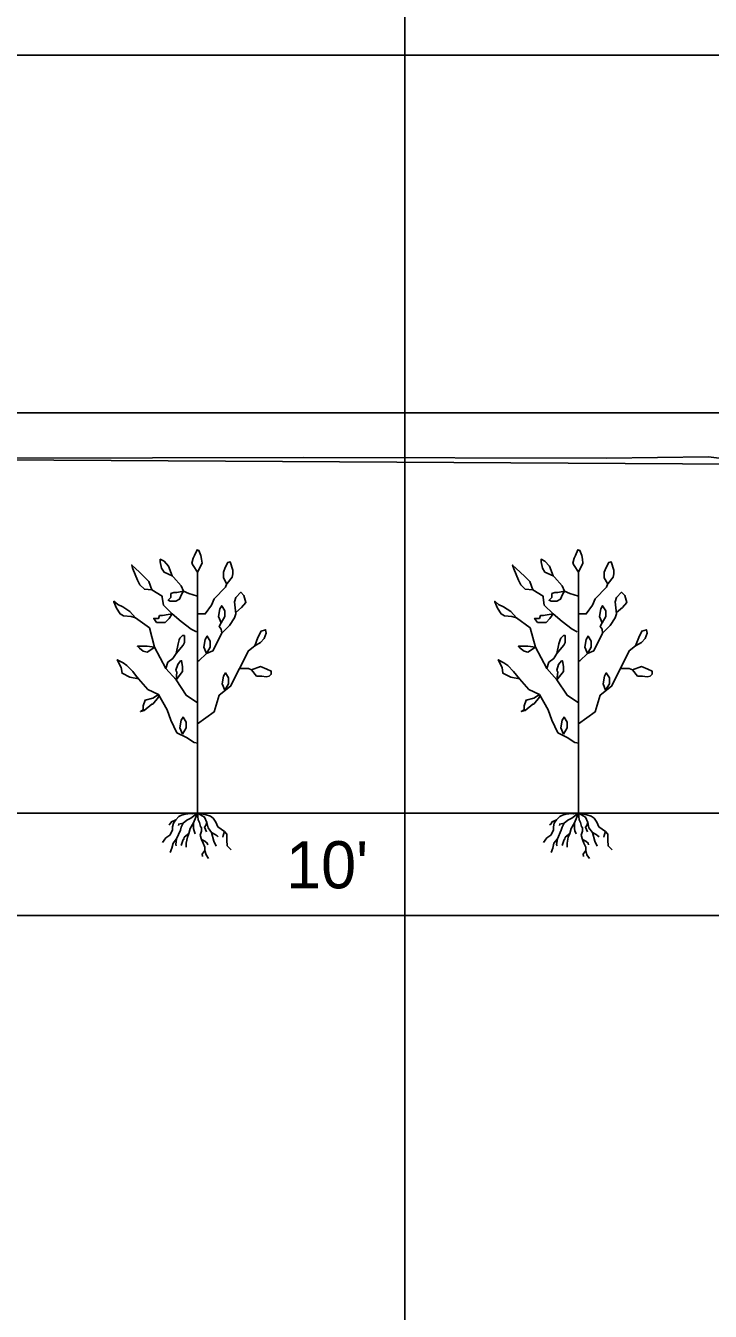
# Model space of a CAD drawing. Extents: x 1578769 to 1579225, y 724002 to 724828.
# Drawn here: x 1578852.46 to 1578859.27, y 724448.54 to 724461.32 of the extents above; entities that cross this region are included whole.
import ezdxf

# ---------------------------------------------------------------- set-up
doc = ezdxf.new("R2010")
doc.units = 0
for name, color, linetype in [('1', 7, 'Continuous'), ('Default', 7, 'Continuous'), ('Old_Level_41', 7, 'Continuous'), ('R_Exist Surface', 7, 'Continuous'), ('R_Fin Surface', 7, 'Continuous')]:
    doc.layers.add(name, color=color, linetype=linetype)

msp = doc.modelspace()

# ---------------------------------------------------------------- linework, layer by layer
at = {"layer": '1'}
for p, q in [((1578851.701, 724461.031), (1578861.706, 724461.031)), ((1578854.17, 724453.49), (1578854.17, 724455.89)), ((1578857.96, 724453.49), (1578857.96, 724455.89)), ((1578854.175, 724453.485), (1578854.177, 724453.489)), ((1578857.965, 724453.485), (1578857.966, 724453.489))]:
    msp.add_line(p, q, dxfattribs=at)
for points in [[(1578854.17, 724455.89), (1578854.126, 724455.953), (1578854.113, 724455.978), (1578854.126, 724456.029), (1578854.139, 724456.054), (1578854.164, 724456.111), (1578854.183, 724456.104), (1578854.202, 724456.054), (1578854.208, 724456.016), (1578854.214, 724455.978)], [(1578857.96, 724455.89), (1578857.916, 724455.953), (1578857.903, 724455.978), (1578857.916, 724456.029), (1578857.929, 724456.054), (1578857.954, 724456.111), (1578857.973, 724456.104), (1578857.992, 724456.054), (1578857.998, 724456.016), (1578858.004, 724455.978)], [(1578853.716, 724455.713), (1578853.64, 724455.719), (1578853.596, 724455.763), (1578853.571, 724455.808), (1578853.526, 724455.921), (1578853.514, 724455.959), (1578853.59, 724455.89), (1578853.634, 724455.846), (1578853.684, 724455.795)], [(1578853.918, 724455.852), (1578853.836, 724455.89), (1578853.81, 724455.928), (1578853.798, 724455.991), (1578853.798, 724456.016), (1578853.836, 724455.997), (1578853.88, 724455.947)], [(1578857.506, 724455.713), (1578857.43, 724455.719), (1578857.386, 724455.763), (1578857.361, 724455.808), (1578857.316, 724455.921), (1578857.304, 724455.959), (1578857.379, 724455.89), (1578857.424, 724455.846), (1578857.474, 724455.795)], [(1578857.708, 724455.852), (1578857.626, 724455.89), (1578857.6, 724455.928), (1578857.588, 724455.991), (1578857.588, 724456.016), (1578857.626, 724455.997), (1578857.67, 724455.947)], [(1578854.031, 724455.7), (1578853.963, 724455.686), (1578853.934, 724455.686), (1578853.905, 724455.676), (1578853.905, 724455.638), (1578853.877, 724455.609), (1578853.896, 724455.6), (1578853.953, 724455.6), (1578853.991, 724455.619), (1578854.01, 724455.666)], [(1578857.821, 724455.7), (1578857.753, 724455.686), (1578857.724, 724455.686), (1578857.695, 724455.676), (1578857.695, 724455.638), (1578857.667, 724455.609), (1578857.686, 724455.6), (1578857.743, 724455.6), (1578857.781, 724455.619), (1578857.8, 724455.666)], [(1578853.918, 724455.473), (1578853.877, 724455.466), (1578853.82, 724455.456), (1578853.791, 724455.456), (1578853.781, 724455.428), (1578853.734, 724455.428), (1578853.762, 724455.389), (1578853.8, 724455.389), (1578853.848, 724455.389), (1578853.886, 724455.428)], [(1578857.708, 724455.473), (1578857.667, 724455.466), (1578857.609, 724455.456), (1578857.581, 724455.456), (1578857.571, 724455.428), (1578857.523, 724455.428), (1578857.552, 724455.389), (1578857.59, 724455.389), (1578857.638, 724455.389), (1578857.676, 724455.428)], [(1578853.956, 724455.081), (1578853.975, 724455.176), (1578853.987, 724455.214), (1578853.993, 724455.233), (1578854.019, 724455.258), (1578854.038, 724455.258), (1578854.038, 724455.189), (1578854.025, 724455.163)], [(1578857.745, 724455.081), (1578857.764, 724455.176), (1578857.777, 724455.214), (1578857.783, 724455.233), (1578857.809, 724455.258), (1578857.828, 724455.258), (1578857.828, 724455.189), (1578857.815, 724455.163)], [(1578853.581, 724454.826), (1578853.495, 724454.845), (1578853.419, 724454.883), (1578853.409, 724454.94), (1578853.371, 724455.017), (1578853.428, 724454.988), (1578853.466, 724454.96), (1578853.524, 724454.902), (1578853.552, 724454.864)], [(1578857.371, 724454.826), (1578857.285, 724454.845), (1578857.208, 724454.883), (1578857.199, 724454.94), (1578857.161, 724455.017), (1578857.218, 724454.988), (1578857.256, 724454.96), (1578857.313, 724454.902), (1578857.342, 724454.864)], [(1578853.956, 724454.816), (1578853.963, 724454.893), (1578853.953, 724454.912), (1578853.972, 724454.969), (1578854.001, 724455.007), (1578854.01, 724455.007), (1578854.02, 724454.95), (1578854.02, 724454.902)], [(1578857.745, 724454.816), (1578857.753, 724454.893), (1578857.743, 724454.912), (1578857.762, 724454.969), (1578857.791, 724455.007), (1578857.8, 724455.007), (1578857.81, 724454.95), (1578857.81, 724454.902)], [(1578853.781, 724454.673), (1578853.724, 724454.635), (1578853.648, 724454.616), (1578853.629, 724454.558), (1578853.629, 724454.52), (1578853.6, 724454.501), (1578853.638, 724454.511), (1578853.715, 724454.577), (1578853.724, 724454.577), (1578853.781, 724454.644)], [(1578857.571, 724454.673), (1578857.514, 724454.635), (1578857.438, 724454.616), (1578857.418, 724454.558), (1578857.418, 724454.52), (1578857.39, 724454.501), (1578857.428, 724454.511), (1578857.504, 724454.577), (1578857.514, 724454.577), (1578857.571, 724454.644)]]:
    msp.add_lwpolyline(points, close=True, dxfattribs=at)
for points in [[(1578854.457, 724455.776), (1578854.426, 724455.833), (1578854.426, 724455.89), (1578854.445, 724455.934), (1578854.47, 724455.984), (1578854.495, 724455.991), (1578854.52, 724455.909), (1578854.52, 724455.871), (1578854.514, 724455.839), (1578854.464, 724455.776)], [(1578858.247, 724455.776), (1578858.216, 724455.833), (1578858.216, 724455.89), (1578858.235, 724455.934), (1578858.26, 724455.984), (1578858.285, 724455.991), (1578858.31, 724455.909), (1578858.31, 724455.871), (1578858.304, 724455.839), (1578858.254, 724455.776)], [(1578854.17, 724455.65), (1578854.082, 724455.675), (1578854.031, 724455.7), (1578854.006, 724455.751), (1578853.93, 724455.839), (1578853.918, 724455.852)], [(1578857.96, 724455.65), (1578857.872, 724455.675), (1578857.821, 724455.7), (1578857.796, 724455.751), (1578857.72, 724455.839), (1578857.708, 724455.852)], [(1578854.158, 724455.296), (1578854.107, 724455.321), (1578854.006, 724455.397), (1578853.918, 724455.473), (1578853.829, 724455.561), (1578853.817, 724455.637), (1578853.817, 724455.65), (1578853.716, 724455.713)], [(1578854.17, 724455.473), (1578854.246, 724455.473), (1578854.309, 724455.561), (1578854.334, 724455.624), (1578854.448, 724455.738), (1578854.46, 724455.776)], [(1578854.549, 724455.473), (1578854.536, 724455.593), (1578854.549, 724455.637), (1578854.599, 724455.688), (1578854.631, 724455.656), (1578854.65, 724455.587), (1578854.606, 724455.536), (1578854.549, 724455.486)], [(1578857.947, 724455.296), (1578857.897, 724455.321), (1578857.796, 724455.397), (1578857.708, 724455.473), (1578857.619, 724455.561), (1578857.607, 724455.637), (1578857.607, 724455.65), (1578857.506, 724455.713)], [(1578857.96, 724455.473), (1578858.036, 724455.473), (1578858.099, 724455.561), (1578858.124, 724455.624), (1578858.238, 724455.738), (1578858.25, 724455.776)], [(1578858.339, 724455.473), (1578858.326, 724455.593), (1578858.339, 724455.637), (1578858.389, 724455.688), (1578858.421, 724455.656), (1578858.44, 724455.587), (1578858.396, 724455.536), (1578858.339, 724455.486)], [(1578853.552, 724455.435), (1578853.508, 724455.448), (1578853.432, 724455.454), (1578853.4, 724455.473), (1578853.362, 724455.53), (1578853.337, 724455.593), (1578853.337, 724455.599), (1578853.375, 724455.568), (1578853.426, 724455.542), (1578853.495, 724455.498), (1578853.552, 724455.435)], [(1578854.404, 724455.384), (1578854.378, 724455.448), (1578854.391, 724455.523), (1578854.41, 724455.555), (1578854.442, 724455.504), (1578854.442, 724455.448), (1578854.404, 724455.384)], [(1578857.342, 724455.435), (1578857.297, 724455.448), (1578857.222, 724455.454), (1578857.19, 724455.473), (1578857.152, 724455.53), (1578857.127, 724455.593), (1578857.127, 724455.599), (1578857.165, 724455.568), (1578857.215, 724455.542), (1578857.285, 724455.498), (1578857.342, 724455.435)], [(1578858.194, 724455.384), (1578858.168, 724455.448), (1578858.181, 724455.523), (1578858.2, 724455.555), (1578858.231, 724455.504), (1578858.231, 724455.448), (1578858.194, 724455.384)], [(1578854.17, 724454.589), (1578854.057, 724454.664), (1578853.956, 724454.816), (1578853.855, 724454.93), (1578853.741, 724455.144), (1578853.691, 724455.334), (1578853.552, 724455.435)], [(1578854.17, 724455.006), (1578854.183, 724455.006), (1578854.259, 724455.081), (1578854.322, 724455.107), (1578854.41, 724455.283), (1578854.486, 724455.359), (1578854.536, 724455.435), (1578854.549, 724455.473)], [(1578857.96, 724454.589), (1578857.846, 724454.664), (1578857.745, 724454.816), (1578857.644, 724454.93), (1578857.531, 724455.144), (1578857.48, 724455.334), (1578857.342, 724455.435)], [(1578857.96, 724455.006), (1578857.973, 724455.006), (1578858.048, 724455.081), (1578858.111, 724455.107), (1578858.2, 724455.283), (1578858.276, 724455.359), (1578858.326, 724455.435), (1578858.339, 724455.473)], [(1578854.41, 724455.283), (1578854.404, 724455.321), (1578854.385, 724455.347), (1578854.404, 724455.384)], [(1578854.738, 724455.157), (1578854.77, 724455.239), (1578854.801, 724455.302), (1578854.846, 724455.315), (1578854.852, 724455.283), (1578854.833, 724455.227), (1578854.795, 724455.189), (1578854.738, 724455.157)], [(1578858.2, 724455.283), (1578858.194, 724455.321), (1578858.175, 724455.347), (1578858.194, 724455.384)], [(1578858.528, 724455.157), (1578858.56, 724455.239), (1578858.591, 724455.302), (1578858.635, 724455.315), (1578858.642, 724455.283), (1578858.623, 724455.227), (1578858.585, 724455.189), (1578858.528, 724455.157)], [(1578853.741, 724455.144), (1578853.667, 724455.151), (1578853.61, 724455.151), (1578853.571, 724455.151), (1578853.59, 724455.131), (1578853.629, 724455.103), (1578853.667, 724455.093), (1578853.743, 724455.141)], [(1578854.17, 724454.381), (1578854.334, 724454.5), (1578854.385, 724454.664), (1578854.498, 724454.753), (1578854.587, 724454.93), (1578854.675, 724455.107), (1578854.738, 724455.157)], [(1578854.259, 724455.081), (1578854.233, 724455.144), (1578854.246, 724455.22), (1578854.265, 724455.252), (1578854.296, 724455.201), (1578854.296, 724455.144), (1578854.259, 724455.081)], [(1578857.531, 724455.144), (1578857.457, 724455.151), (1578857.399, 724455.151), (1578857.361, 724455.151), (1578857.38, 724455.131), (1578857.418, 724455.103), (1578857.457, 724455.093), (1578857.533, 724455.141)], [(1578857.96, 724454.381), (1578858.124, 724454.5), (1578858.175, 724454.664), (1578858.288, 724454.753), (1578858.377, 724454.93), (1578858.465, 724455.107), (1578858.528, 724455.157)], [(1578858.048, 724455.081), (1578858.023, 724455.144), (1578858.036, 724455.22), (1578858.055, 724455.252), (1578858.086, 724455.201), (1578858.086, 724455.144), (1578858.048, 724455.081)], [(1578853.855, 724454.93), (1578853.874, 724454.993), (1578853.924, 724455.031), (1578853.956, 724455.081)], [(1578857.644, 724454.93), (1578857.663, 724454.993), (1578857.714, 724455.031), (1578857.745, 724455.081)], [(1578854.44, 724454.716), (1578854.414, 724454.779), (1578854.427, 724454.855), (1578854.446, 724454.886), (1578854.477, 724454.836), (1578854.477, 724454.779), (1578854.44, 724454.716)], [(1578854.587, 724454.93), (1578854.65, 724454.93), (1578854.675, 724454.93), (1578854.707, 724454.917)], [(1578854.707, 724454.917), (1578854.795, 724454.949), (1578854.858, 724454.923), (1578854.902, 724454.904), (1578854.902, 724454.873), (1578854.883, 724454.854), (1578854.852, 724454.848), (1578854.808, 724454.854), (1578854.757, 724454.854), (1578854.707, 724454.917)], [(1578858.229, 724454.716), (1578858.204, 724454.779), (1578858.217, 724454.855), (1578858.236, 724454.886), (1578858.267, 724454.836), (1578858.267, 724454.779), (1578858.229, 724454.716)], [(1578858.377, 724454.93), (1578858.44, 724454.93), (1578858.465, 724454.93), (1578858.496, 724454.917)], [(1578858.496, 724454.917), (1578858.585, 724454.949), (1578858.648, 724454.923), (1578858.692, 724454.904), (1578858.692, 724454.873), (1578858.673, 724454.854), (1578858.642, 724454.848), (1578858.597, 724454.854), (1578858.547, 724454.854), (1578858.496, 724454.917)], [(1578854.173, 724454.186), (1578854.135, 724454.195), (1578854.058, 724454.243), (1578853.963, 724454.291), (1578853.905, 724454.415), (1578853.867, 724454.52), (1578853.781, 724454.673), (1578853.676, 724454.721), (1578853.581, 724454.826), (1578853.581, 724454.826)], [(1578857.963, 724454.186), (1578857.924, 724454.195), (1578857.848, 724454.243), (1578857.753, 724454.291), (1578857.695, 724454.415), (1578857.657, 724454.52), (1578857.571, 724454.673), (1578857.466, 724454.721), (1578857.371, 724454.826), (1578857.371, 724454.826)], [(1578854.019, 724454.276), (1578853.994, 724454.339), (1578854.007, 724454.415), (1578854.026, 724454.447), (1578854.057, 724454.396), (1578854.057, 724454.339), (1578854.019, 724454.276)], [(1578857.809, 724454.276), (1578857.784, 724454.339), (1578857.797, 724454.415), (1578857.816, 724454.447), (1578857.847, 724454.396), (1578857.847, 724454.339), (1578857.809, 724454.276)], [(1578854.17, 724453.49), (1578854.119, 724453.484), (1578854.103, 724453.488), (1578854.045, 724453.48), (1578854.01, 724453.472), (1578853.983, 724453.457), (1578853.952, 724453.426), (1578853.929, 724453.391), (1578853.921, 724453.356), (1578853.921, 724453.325), (1578853.905, 724453.29), (1578853.894, 724453.274), (1578853.855, 724453.247), (1578853.82, 724453.201)], [(1578854.17, 724453.49), (1578854.103, 724453.441), (1578854.064, 724453.422), (1578854.026, 724453.391), (1578854.006, 724453.352), (1578853.998, 724453.321), (1578853.96, 724453.235), (1578853.925, 724453.193), (1578853.913, 724453.142), (1578853.898, 724453.1)], [(1578854.17, 724453.49), (1578854.13, 724453.395), (1578854.095, 724453.34), (1578854.084, 724453.29), (1578854.068, 724453.251), (1578854.057, 724453.193), (1578854.057, 724453.154)], [(1578854.17, 724453.49), (1578854.254, 724453.474), (1578854.297, 724453.461), (1578854.324, 724453.441), (1578854.352, 724453.402), (1578854.371, 724453.356), (1578854.437, 724453.309), (1578854.46, 724453.282), (1578854.46, 724453.224), (1578854.464, 724453.166), (1578854.503, 724453.127)], [(1578854.17, 724453.49), (1578854.239, 724453.453), (1578854.262, 724453.399), (1578854.274, 724453.344), (1578854.309, 724453.298), (1578854.332, 724453.212), (1578854.355, 724453.162)], [(1578854.17, 724453.49), (1578854.177, 724453.426), (1578854.189, 724453.399), (1578854.2, 724453.36), (1578854.208, 724453.344), (1578854.208, 724453.313), (1578854.196, 724453.274), (1578854.208, 724453.228), (1578854.224, 724453.193), (1578854.243, 724453.154), (1578854.243, 724453.119), (1578854.255, 724453.076), (1578854.278, 724453.041)], [(1578857.96, 724453.49), (1578857.909, 724453.484), (1578857.893, 724453.488), (1578857.835, 724453.48), (1578857.8, 724453.472), (1578857.773, 724453.457), (1578857.742, 724453.426), (1578857.719, 724453.391), (1578857.711, 724453.356), (1578857.711, 724453.325), (1578857.695, 724453.29), (1578857.684, 724453.274), (1578857.645, 724453.247), (1578857.61, 724453.201)], [(1578857.96, 724453.49), (1578857.893, 724453.441), (1578857.854, 724453.422), (1578857.816, 724453.391), (1578857.796, 724453.352), (1578857.788, 724453.321), (1578857.75, 724453.235), (1578857.715, 724453.193), (1578857.703, 724453.142), (1578857.687, 724453.1)], [(1578857.96, 724453.49), (1578857.92, 724453.395), (1578857.885, 724453.34), (1578857.874, 724453.29), (1578857.858, 724453.251), (1578857.847, 724453.193), (1578857.847, 724453.154)], [(1578857.96, 724453.49), (1578858.044, 724453.474), (1578858.087, 724453.461), (1578858.114, 724453.441), (1578858.141, 724453.402), (1578858.161, 724453.356), (1578858.227, 724453.309), (1578858.25, 724453.282), (1578858.25, 724453.224), (1578858.254, 724453.166), (1578858.293, 724453.127)], [(1578857.96, 724453.49), (1578858.029, 724453.453), (1578858.052, 724453.399), (1578858.064, 724453.344), (1578858.099, 724453.298), (1578858.122, 724453.212), (1578858.145, 724453.162)], [(1578857.96, 724453.49), (1578857.967, 724453.426), (1578857.978, 724453.399), (1578857.99, 724453.36), (1578857.998, 724453.344), (1578857.998, 724453.313), (1578857.986, 724453.274), (1578857.998, 724453.228), (1578858.013, 724453.193), (1578858.033, 724453.154), (1578858.033, 724453.119), (1578858.044, 724453.076), (1578858.068, 724453.041)], [(1578853.952, 724453.426), (1578853.909, 724453.406), (1578853.894, 724453.383), (1578853.882, 724453.375)], [(1578854.026, 724453.391), (1578853.983, 724453.383), (1578853.979, 724453.367)], [(1578854.13, 724453.395), (1578854.13, 724453.34), (1578854.134, 724453.317), (1578854.146, 724453.286)], [(1578854.262, 724453.399), (1578854.251, 724453.367), (1578854.239, 724453.352), (1578854.258, 724453.305)], [(1578857.742, 724453.426), (1578857.699, 724453.406), (1578857.684, 724453.383), (1578857.672, 724453.375)], [(1578857.816, 724453.391), (1578857.773, 724453.383), (1578857.769, 724453.367)], [(1578857.92, 724453.395), (1578857.92, 724453.34), (1578857.924, 724453.317), (1578857.936, 724453.286)], [(1578858.052, 724453.399), (1578858.041, 724453.367), (1578858.029, 724453.352), (1578858.048, 724453.305)], [(1578853.96, 724453.235), (1578853.952, 724453.181), (1578853.956, 724453.166)], [(1578854.084, 724453.29), (1578854.037, 724453.251), (1578854.033, 724453.232), (1578854.026, 724453.228), (1578854.006, 724453.169)], [(1578854.208, 724453.228), (1578854.243, 724453.212), (1578854.266, 724453.193), (1578854.27, 724453.177)], [(1578854.309, 724453.298), (1578854.344, 724453.278), (1578854.363, 724453.267), (1578854.375, 724453.255)], [(1578854.437, 724453.309), (1578854.425, 724453.27), (1578854.421, 724453.251)], [(1578857.75, 724453.235), (1578857.742, 724453.181), (1578857.746, 724453.166)], [(1578857.874, 724453.29), (1578857.827, 724453.251), (1578857.823, 724453.232), (1578857.816, 724453.228), (1578857.796, 724453.169)], [(1578857.998, 724453.228), (1578858.033, 724453.212), (1578858.056, 724453.193), (1578858.06, 724453.177)], [(1578858.099, 724453.298), (1578858.134, 724453.278), (1578858.153, 724453.267), (1578858.165, 724453.255)], [(1578858.227, 724453.309), (1578858.215, 724453.27), (1578858.211, 724453.251)], [(1578854.243, 724453.119), (1578854.216, 724453.084), (1578854.22, 724453.061)], [(1578858.033, 724453.119), (1578858.006, 724453.084), (1578858.01, 724453.061)]]:
    msp.add_lwpolyline(points, dxfattribs=at)
at = {"layer": 'Default'}
msp.add_lwpolyline([(1578841.23, 724457.071), (1578842.26, 724457.059), (1578863.33, 724456.943), (1578874.29, 724456.885), (1578876.4, 724454.796), (1578883.17, 724446.782), (1578901.02, 724441.71), (1578903.45, 724441.029), (1578909.92, 724441.377), (1578926.32, 724442.247), (1578964.09, 724446.554), (1578966.7, 724446.865), (1578977.39, 724447.842), (1578995.69, 724449.505), (1578999.6, 724449.841), (1579038.5, 724453.366)], dxfattribs=at)
at = {"layer": 'Old_Level_41'}
msp.add_line((1578856.23, 724437.474), (1578856.23, 724467.474), dxfattribs=at)
for points in [[(1578921.23, 724457.474), (1578821.23, 724457.474)], [(1578821.23, 724452.474), (1578921.23, 724452.474)]]:
    msp.add_lwpolyline(points, dxfattribs=at)
at = {"layer": 'R_Exist Surface'}
msp.add_lwpolyline([(1578821.23, 724457.096), (1578841.203, 724457.073), (1578846.234, 724457.073), (1578848.249, 724457.093), (1578849.212, 724457.015), (1578855.223, 724457.028), (1578858.238, 724457.022), (1578859.252, 724457.035), (1578860.202, 724456.917), (1578863.142, 724456.957), (1578870.155, 724456.957), (1578871.148, 724456.899), (1578871.421, 724456.873), (1578874.244, 724456.899), (1578875.116, 724456.014), (1578876.183, 724454.946), (1578880.212, 724450.271), (1578880.86, 724449.513), (1578883.256, 724446.747), (1578884.97, 724446.281), (1578895.079, 724443.387), (1578896.257, 724443.057)], dxfattribs=at)
at = {"layer": 'R_Fin Surface'}
msp.add_line((1578851.701, 724453.49), (1578861.701, 724453.49), dxfattribs=at)
msp.add_line((1578851.701, 724453.49), (1578861.701, 724453.49), dxfattribs=at)

# ---------------------------------------------------------------- texts
at = {"layer": '1'}
msp.add_text("10'", height=0.4687, dxfattribs=at).set_placement((1578855.05, 724452.744))

doc.saveas('drawing.dxf')
